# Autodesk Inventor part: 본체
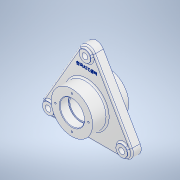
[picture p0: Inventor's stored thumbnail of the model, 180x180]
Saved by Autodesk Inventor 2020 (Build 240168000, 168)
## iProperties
Created: 2023-04
Part Number: 본체
Material: 알루미늄 6061
Document SubType Name: Modeling
Designer: oem
Density: 2.7 g/cm^3
Appearance: 알루미늄 - 평지
Mass: 1219.03 g
Surface Area: 640.875 cm^2
Volume: 451.494 cm^3
Author: oem
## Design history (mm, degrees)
sketch "스케치1" dims "d0" = 164
  geometry: C1 r 16 at (0, 82); C2 r 16 at (-71.014, -41); C3 r 16 at (71.014, -41); 2 further points
  constraints: 3 centre point, 1 coincident, 1 vertical alignment, 9 other
  dimensions: "d1" = 32 diameter of C1; "d6" = 360 deg dimension on point (0, 0) C1.centre (derived)
extrude "돌출1" new body sketch "스케치1" stored distance "d2" = 18; taper "d3" = 0 deg
sketch "스케치2"
  geometry: L1 (0, 114)-(-98.727, -57); L2 (-98.727, -57)-(98.727, -57); L3 (0, 114)-(98.727, -57); C1 r 16 at (0, 82) reference; C2 r 16 at (-71.014, -41) reference; C3 r 16 at (71.014, -41) reference; 7 further points
  constraints: 6 end point, 6 tangent, 1 horizontal
extrude "돌출2" join sketch "스케치2" stored distance "d8" = 18; taper "d9" = 0 deg
sketch "스케치3"
  geometry: C1 r 40 at (0, 0); 1 further point
  constraints: 1 centre point, 1 coincident
  dimensions: "d10" = 80 diameter of C1
extrude "돌출3" join sketch "스케치3" distance "d11" = 29; taper "d12" = 0 deg
sketch "스케치4"
  geometry: C1 r 45 at (0, 0); 1 further point
  constraints: 1 centre point, 1 coincident
  dimensions: "d13" = 90 diameter of C1
extrude "돌출4" join sketch "스케치4" distance "d14" = 5; taper "d15" = 0 deg
sketch "스케치5"
  geometry: C1 r 45 at (0, 0) reference; C2 r 40 at (0, 0)
  constraints: 1 centre point, 1 coincident
  dimensions: "d16" = 80 diameter of C2
extrude "돌출5" join sketch "스케치5" distance "d17" = 18; taper "d18" = 0 deg
sketch "스케치6"
  geometry: L1 (-40, -32)-(40, -32) reference; L2 (0, -32)-(0, 38); L3 (40, 38)-(-40, 38) reference; L4 (0, -32)-(23.5, -32); L5 (23.5, -32)-(23.5, -15); L6 (23.5, -15)-(21, -15); L7 (21, -15)-(21, 21); L8 (21, 21)-(23.5, 21); L9 (23.5, 21)-(23.5, 38); L10 (23.5, 38)-(0, 38); 1 further point
  constraints: 16 end point, 4 perpendicular, 2 midpoint, 2 point on line, 1 collinear, 1 vertical
  dimensions: "d19" = 47 diameter of L9 L2; "d20" = 42 diameter of L7 L2; "d21" = 47 diameter of L5 L2; "d22" = 17 distance between parallel lines of L3 L8; "d23" = 17 distance between parallel lines of L1 L6
revolve "회전1" sketch "스케치6" stored, may be unused: angle "d24" = 90 deg
sketch "스케치7" dims "d25" = 64
  geometry: C1 r 40 at (0, 0) reference; 2 further points
  constraints: 1 coincident, 1 vertical alignment, 2 other
hole "구멍1" sketch "스케치7" at (0, 32) diameter "d26" = 3.242; stored, may be unused: countersink angle "d30" = 90 deg, drill point angle "d32" = 118 deg; dims "d27" = 8, "d28" = 4, "d29" = 2, "d31" = 10
node "작업 평면1"
sketch "스케치8"
  geometry: C1 r 11 at (71.014, -41); A1 r 16 centre (71.014, -41) between (71.014, -57) and (84.87, -33) reference
  constraints: 1 centre point, 1 coincident
  dimensions: "d36" = 22 diameter of C1
extrude "돌출6" join sketch "스케치8" distance "d37" = 4; taper "d38" = 0 deg
sketch "스케치9"
  geometry: C1 r 11 at (0, 0) reference; C2 r 5.5 at (0, 0); 1 further point
  constraints: 1 centre point, 1 coincident
  dimensions: "d39" = 11 diameter of C2
extrude "돌출7" cut sketch "스케치9" extent not by distance; stored distance "d40" = 0; taper "d41" = 0 deg
node "작업 평면2"
sketch "스케치10"
  geometry: 2 further points
  constraints: 1 vertical alignment, 1 other
  dimensions: "d46" = 60 distance of point (0, 0) point (0, 60)
feature "엠보싱1" sketch "스케치10" dims "d2" = 18, "d3" = 0, "d11" = 29, "d12" = 0, "d47" = 0.5, "d48" = 0
fillet "모깎기1" dims "d49" = 0.6
fillet "모깎기2" dims "d50" = 3
chamfer "모따기1" distance "d51" = 1; stored, may be unused: second distance "d52" = 2, angle "d53" = 45 deg
node "솔리드1"
pattern_circular "원형 패턴1" dims angle "d34" = 360 deg
mirror "미러1"
pattern_circular "원형 패턴2" dims angle "d43" = 360 deg
feature "A9D066F2-1C7D-4E18-AEED-F7BC21143FA4" dims "d26" = 3.242, "d27" = 8, "d28" = 4, "d29" = 2, "d30" = 90 deg, "d31" = 10, "d32" = 118 deg
other parameters: "d45" = 45.75
